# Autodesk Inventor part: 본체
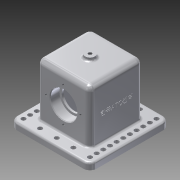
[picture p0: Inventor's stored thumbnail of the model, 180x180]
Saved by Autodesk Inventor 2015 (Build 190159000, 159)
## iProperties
Created: 2018-11
Part Number: 본체
Material: 알루미늄 6061
Document SubType Name: Modeling
Designer: now
Density: 2.7 g/cm^3
Appearance: 알루미늄 - 평지
Mass: 1016.94 g
Surface Area: 777.733 cm^2
Volume: 376.643 cm^3
Author: now
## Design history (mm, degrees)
sketch "스케치1"
  geometry: L1 (-60, -60)-(60, -60); L2 (60, -60)-(60, 60); L3 (60, 60)-(-60, 60); L4 (-60, 60)-(-60, -60); L5 (-60, -60)-(60, 60); L6 (60, -60)-(-60, 60); 1 further point
  constraints: 12 end point, 2 midpoint, 2 parallel, 1 horizontal, 1 perpendicular
  dimensions: "d0" = 120 distance of L3.end L1.start; "d1" = 120 distance of L2.end L3.end
extrude "돌출1" new body sketch "스케치1" distance "d2" = 10; taper "d3" = 0 deg
sketch "스케치2"
  geometry: L1 (-40, -40)-(40, -40); L2 (40, -40)-(40, 40); L3 (40, 40)-(-40, 40); L4 (-40, 40)-(-40, -40); L5 (-40, -40)-(40, 40); L6 (40, -40)-(-40, 40); 1 further point
  constraints: 12 end point, 2 midpoint, 2 parallel, 1 horizontal, 1 perpendicular
  dimensions: "d4" = 80 distance of L3.end L1.start; "d5" = 80 distance of L2.end L3.end
extrude "돌출2" join sketch "스케치2" distance "d6" = 80; taper "d7" = 0 deg
node "작업 평면1"
sketch "스케치3"
  geometry: C1 r 7.5 at (0, 0); 1 further point
  constraints: 1 centre point, 1 coincident
  dimensions: "d9" = 15 diameter of C1
extrude "돌출3" join sketch "스케치3" stored distance "d10" = 80; taper "d11" = 0 deg
sketch "스케치4"
  geometry: C1 r 7.5 at (0, 0) reference
hole "구멍1" sketch "스케치4" at (0, 0) diameter "d12" = 4.917; stored, may be unused: countersink angle "d16" = 90 deg, drill point angle "d18" = 118 deg; dims "d13" = 12, "d14" = 4, "d15" = 2, "d17" = 45
sketch "스케치5"
  geometry: L1 (30, -23)-(-30, -23); L2 (-30, -23)-(-30, 23); L3 (-30, 23)-(30, 23); L4 (30, 23)-(30, -23); L5 (30, -23)-(-30, 23); L6 (-30, -23)-(30, 23); 1 further point
  constraints: 12 end point, 2 midpoint, 2 parallel, 1 horizontal, 1 perpendicular
  dimensions: "d19" = 60 distance of L1.start L1.end; "d20" = 46 distance of L1.end L2.end
extrude "돌출4" cut sketch "스케치5" distance "d21" = 80; taper "d22" = 0 deg
fillet "모깎기1" dims "d23" = 3
fillet "모깎기2" dims "d24" = 3
sketch "스케치6"
  geometry: L1 (-20, -10)-(100, -10) reference; C1 r 16.5 at (40, 38); 1 further point
  constraints: 1 centre point
  dimensions: "d25" = 33 diameter of C1; "d26" = 48 distance from line of L1 C1.centre
extrude "돌출5" cut sketch "스케치6" stored distance "d27" = 80; taper "d28" = 0 deg
sketch "스케치7"
  geometry: C1 r 16.5 at (40, 38) reference; C2 r 20 at (40, 38); 1 further point
  constraints: 1 centre point, 1 coincident
  dimensions: "d29" = 40 diameter of C2
extrude "돌출6" cut sketch "스케치7" distance "d30" = 14; taper "d31" = 0 deg
chamfer "모따기1" distance "d32" = 1; stored, may be unused: second distance "d33" = 2, angle "d34" = 45 deg
chamfer "모따기2" distance "d35" = 1; stored, may be unused: second distance "d36" = 2, angle "d37" = 45 deg
sketch "스케치8"
  geometry: C1 r 21 at (40, 38) reference; C2 r 20 at (40, 38) reference; 2 further points
  constraints: 1 vertical alignment
  dimensions: "d38" = 26 distance of point (40, 64) C2.centre
hole "구멍2" sketch "스케치8" at (40, 64) diameter "d39" = 3.242; stored, may be unused: countersink angle "d43" = 90 deg, drill point angle "d45" = 118 deg; dims "d40" = 8, "d41" = 4, "d42" = 2, "d44" = 10
fillet "모깎기3" dims "d49" = 10
fillet "모깎기4" dims "d50" = 3
sketch "스케치9"
  geometry: C1 r 3.3 at (-50, -50); A1 r 7 centre (-50, -50) between (-57, -50) and (-50, -57) reference; 1 further point
  constraints: 1 centre point, 1 coincident
  dimensions: "d51" = 6.6 diameter of C1
extrude "돌출7" cut sketch "스케치9" stored distance "d52" = 10; taper "d53" = 0 deg
fillet "모깎기5" dims "d72" = 8
fillet "모깎기6" dims "d73" = 8
fillet "모깎기7" dims "d74" = 3
sketch "스케치11"
  geometry: L1 (82, -18)-(82, 82) reference; 3 further points
  constraints: 1 horizontal alignment, 1 midpoint, 1 other
  dimensions: "d75" = 48 distance from line of L1 point (34, 32)
feature "엠보싱1" sketch "스케치11" dims "d0" = 120, "d1" = 120, "d76" = 0.5, "d77" = 0
node "솔리드1"
mirror "대칭1"
pattern_circular "원형 패턴1" dims angle "d47" = 360 deg
mirror "대칭2"
pattern_linear "직사각형 패턴2" dims "d62" = 10
pattern_linear "직사각형 패턴3" dims "d68" = 25
other parameters: "d8" = 95
